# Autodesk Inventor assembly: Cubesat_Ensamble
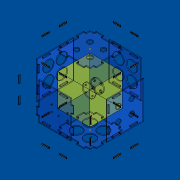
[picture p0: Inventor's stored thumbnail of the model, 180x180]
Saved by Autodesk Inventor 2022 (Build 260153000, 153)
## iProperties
Created: 2022-05
Part Number: Cubesat_Ensamble
Document SubType Name: Assembly
Designer: valen
Author: valen
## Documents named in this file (11)
- G:\Unidades compartidas\PROYECTO PANAMA\Archivos para pagina web\Estandar CubeSat - Programa AVES\3D - MODELS\IPT(Autodesk Inventor)\Cubesat_Ensamble_explosionado.iam
- G:\Unidades compartidas\PROYECTO PANAMA\Archivos para pagina web\Estandar CubeSat - Programa AVES\3D - MODELS\IPT(Autodesk Inventor)\Volumen interno .ipt
- G:\Unidades compartidas\PROYECTO PANAMA\Archivos para pagina web\Estandar CubeSat - Programa AVES\3D - MODELS\IPT(Autodesk Inventor)\1.Frontal.ipt
- G:\Unidades compartidas\PROYECTO PANAMA\Archivos para pagina web\Estandar CubeSat - Programa AVES\3D - MODELS\IPT(Autodesk Inventor)\3.Posterior.ipt
- G:\Unidades compartidas\PROYECTO PANAMA\Archivos para pagina web\Estandar CubeSat - Programa AVES\3D - MODELS\IPT(Autodesk Inventor)\2.Lateral derecha .ipt
- G:\Unidades compartidas\PROYECTO PANAMA\Archivos para pagina web\Estandar CubeSat - Programa AVES\3D - MODELS\IPT(Autodesk Inventor)\4.Lateral izquierda.ipt
- G:\Unidades compartidas\PROYECTO PANAMA\Archivos para pagina web\Estandar CubeSat - Programa AVES\3D - MODELS\IPT(Autodesk Inventor)\6.Inferior.ipt
- G:\Unidades compartidas\PROYECTO PANAMA\Archivos para pagina web\Estandar CubeSat - Programa AVES\3D - MODELS\IPT(Autodesk Inventor)\5.Superior.ipt
- G:\Unidades compartidas\PROYECTO PANAMA\Archivos para pagina web\Estandar CubeSat - Programa AVES\3D - MODELS\IPT(Autodesk Inventor)\7. Arandela.ipt
- G:\Unidades compartidas\PROYECTO PANAMA\Archivos para pagina web\Estandar CubeSat - Programa AVES\3D - MODELS\IPT(Autodesk Inventor)\8. Soporte tuercas.ipt
- G:\Unidades compartidas\PROYECTO PANAMA\Archivos para pagina web\Estandar CubeSat - Programa AVES\3D - MODELS\IPT(Autodesk Inventor)\Oring.ipt
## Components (29 placed, 10 different names)
1. Volumen interno :1 — Flush:1, Mate:1, Flush:2, Flush:3, Flush:4, Mate:2, Flush:5, Mate:3, Mate:4, Mate:5, Mate:6, Mate:7, Flush:7, Flush:8, Mate:8, Flush:9
2. 1.Frontal:1 — Flush:1, Mate:1, Flush:3, Flush:10, Mate:16, Mate:18, Mate:20, Mate:22, Mate:24
3. 3.Posterior:1 — Flush:4, Mate:2, Flush:5, Mate:26, Mate:28, Mate:30, Mate:32, Mate:34, Mate:36
4. 2.Lateral derecha :1 — Mate:3, Mate:4, Mate:5, Flush:6, Mate:23, Flush:14, Mate:25, Flush:15, Mate:27, Flush:16, Mate:29, Flush:17, Mate:39, Flush:22, Mate:41, Flush:23, Mate:47, Flush:26, Mate:49, Flush:27
5. 4.Lateral izquierda:1 — Mate:6, Mate:7, Flush:6, Mate:17, Flush:11, Mate:35, Flush:20, Mate:37, Flush:21, Mate:43, Flush:24, Mate:45, Flush:25, Mate:51, Flush:28, Mate:53, Flush:29
6. 6.Inferior:1 — Flush:7, Flush:8, Mate:8, Mate:11, Mate:12, Mate:13, Mate:19, Flush:12, Mate:21, Flush:13, Mate:31, Flush:18, Mate:33, Flush:19, Mate:46, Mate:48, Mate:50, Mate:52
7. 5.Superior:1 — Flush:9, Mate:38, Mate:40, Mate:42, Mate:44
8. 7. Arandela:1 — Mate:11, Mate:12, Mate:13, Mate:14, Mate:15
9. 8. Soporte tuercas:1 — Mate:14, Mate:15
10. Oring:1 — Flush:10
11. Oring:2 — Mate:16, Mate:17, Flush:11
12. Oring:3 — Mate:18, Mate:19, Flush:12
13. Oring:4 — Mate:20, Mate:21, Flush:13
14. Oring:5 — Mate:22, Mate:23, Flush:14
15. Oring:6 — Mate:24, Mate:25, Flush:15
16. Oring:7 — Mate:26, Mate:27, Flush:16
17. Oring:8 — Mate:36, Mate:37, Flush:21
18. Oring:9 — Mate:32, Mate:33, Flush:19
19. Oring:10 — Mate:34, Mate:35, Flush:20
20. Oring:11 — Mate:30, Mate:31, Flush:18
21. Oring:12 — Mate:28, Mate:29, Flush:17
22. Oring:13 — Mate:40, Mate:41, Flush:23
23. Oring:14 — Mate:42, Mate:43, Flush:24
24. Oring:15 — Mate:38, Mate:39, Flush:22
25. Oring:16 — Mate:44, Mate:45, Flush:25
26. Oring:17 — Mate:48, Mate:49, Flush:27
27. Oring:18 — Mate:46, Mate:47, Flush:26
28. Oring:19 — Mate:52, Mate:53, Flush:29
29. Oring:20 — Mate:50, Mate:51, Flush:28
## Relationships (80: Mate 51, Flush 29)
- Flush:1: Volumen interno :1 ↔ 1.Frontal:1
- Mate:1: Volumen interno :1 ↔ 1.Frontal:1
- Flush:2: Volumen interno :1
- Flush:3: Volumen interno :1 ↔ 1.Frontal:1
- Flush:4: Volumen interno :1 ↔ 3.Posterior:1
- Mate:2: Volumen interno :1 ↔ 3.Posterior:1
- Flush:5: Volumen interno :1 ↔ 3.Posterior:1
- Mate:3: Volumen interno :1 ↔ 2.Lateral derecha :1
- Mate:4: Volumen interno :1 ↔ 2.Lateral derecha :1
- Mate:5: Volumen interno :1 ↔ 2.Lateral derecha :1
- Mate:6: Volumen interno :1 ↔ 4.Lateral izquierda:1
- Mate:7: Volumen interno :1 ↔ 4.Lateral izquierda:1
- Flush:6: 2.Lateral derecha :1 ↔ 4.Lateral izquierda:1
- Flush:7: Volumen interno :1 ↔ 6.Inferior:1
- Flush:8: Volumen interno :1 ↔ 6.Inferior:1
- Mate:8: Volumen interno :1 ↔ 6.Inferior:1
- Flush:9: Volumen interno :1 ↔ 5.Superior:1
- Mate:11: 6.Inferior:1 ↔ 7. Arandela:1
- Mate:12: 6.Inferior:1 ↔ 7. Arandela:1
- Mate:13: 6.Inferior:1 ↔ 7. Arandela:1
- Mate:14: 7. Arandela:1 ↔ 8. Soporte tuercas:1
- Mate:15: 7. Arandela:1 ↔ 8. Soporte tuercas:1
- Flush:10: 1.Frontal:1 ↔ Oring:1
- Mate:16: 1.Frontal:1 ↔ Oring:2
- Mate:17: 4.Lateral izquierda:1 ↔ Oring:2
- Flush:11: 4.Lateral izquierda:1 ↔ Oring:2
- Mate:18: 1.Frontal:1 ↔ Oring:3
- Mate:19: 6.Inferior:1 ↔ Oring:3
- Flush:12: 6.Inferior:1 ↔ Oring:3
- Mate:20: 1.Frontal:1 ↔ Oring:4
- Mate:21: 6.Inferior:1 ↔ Oring:4
- Flush:13: 6.Inferior:1 ↔ Oring:4
- Mate:22: 1.Frontal:1 ↔ Oring:5
- Mate:23: 2.Lateral derecha :1 ↔ Oring:5
- Flush:14: 2.Lateral derecha :1 ↔ Oring:5
- Mate:24: 1.Frontal:1 ↔ Oring:6
- Mate:25: 2.Lateral derecha :1 ↔ Oring:6
- Flush:15: 2.Lateral derecha :1 ↔ Oring:6
- Mate:26: 3.Posterior:1 ↔ Oring:7
- Mate:27: 2.Lateral derecha :1 ↔ Oring:7
- Flush:16: 2.Lateral derecha :1 ↔ Oring:7
- Mate:28: 3.Posterior:1 ↔ Oring:12
- Mate:29: 2.Lateral derecha :1 ↔ Oring:12
- Flush:17: 2.Lateral derecha :1 ↔ Oring:12
- Mate:30: 3.Posterior:1 ↔ Oring:11
- Mate:31: 6.Inferior:1 ↔ Oring:11
- Flush:18: 6.Inferior:1 ↔ Oring:11
- Mate:32: 3.Posterior:1 ↔ Oring:9
- Mate:33: 6.Inferior:1 ↔ Oring:9
- Flush:19: 6.Inferior:1 ↔ Oring:9
- Mate:34: 3.Posterior:1 ↔ Oring:10
- Mate:35: 4.Lateral izquierda:1 ↔ Oring:10
- Flush:20: 4.Lateral izquierda:1 ↔ Oring:10
- Mate:36: 3.Posterior:1 ↔ Oring:8
- Mate:37: 4.Lateral izquierda:1 ↔ Oring:8
- Flush:21: 4.Lateral izquierda:1 ↔ Oring:8
- Mate:38: 5.Superior:1 ↔ Oring:15
- Mate:39: 2.Lateral derecha :1 ↔ Oring:15
- Flush:22: 2.Lateral derecha :1 ↔ Oring:15
- Mate:40: 5.Superior:1 ↔ Oring:13
- Mate:41: 2.Lateral derecha :1 ↔ Oring:13
- Flush:23: 2.Lateral derecha :1 ↔ Oring:13
- Mate:42: 5.Superior:1 ↔ Oring:14
- Mate:43: 4.Lateral izquierda:1 ↔ Oring:14
- Flush:24: 4.Lateral izquierda:1 ↔ Oring:14
- Mate:44: 5.Superior:1 ↔ Oring:16
- Mate:45: 4.Lateral izquierda:1 ↔ Oring:16
- Flush:25: 4.Lateral izquierda:1 ↔ Oring:16
- Mate:46: 6.Inferior:1 ↔ Oring:18
- Mate:47: 2.Lateral derecha :1 ↔ Oring:18
- Flush:26: 2.Lateral derecha :1 ↔ Oring:18
- Mate:48: 6.Inferior:1 ↔ Oring:17
- Mate:49: 2.Lateral derecha :1 ↔ Oring:17
- Flush:27: 2.Lateral derecha :1 ↔ Oring:17
- Mate:50: 6.Inferior:1 ↔ Oring:20
- Mate:51: 4.Lateral izquierda:1 ↔ Oring:20
- Flush:28: 4.Lateral izquierda:1 ↔ Oring:20
- Mate:52: 6.Inferior:1 ↔ Oring:19
- Mate:53: 4.Lateral izquierda:1 ↔ Oring:19
- Flush:29: 4.Lateral izquierda:1 ↔ Oring:19
